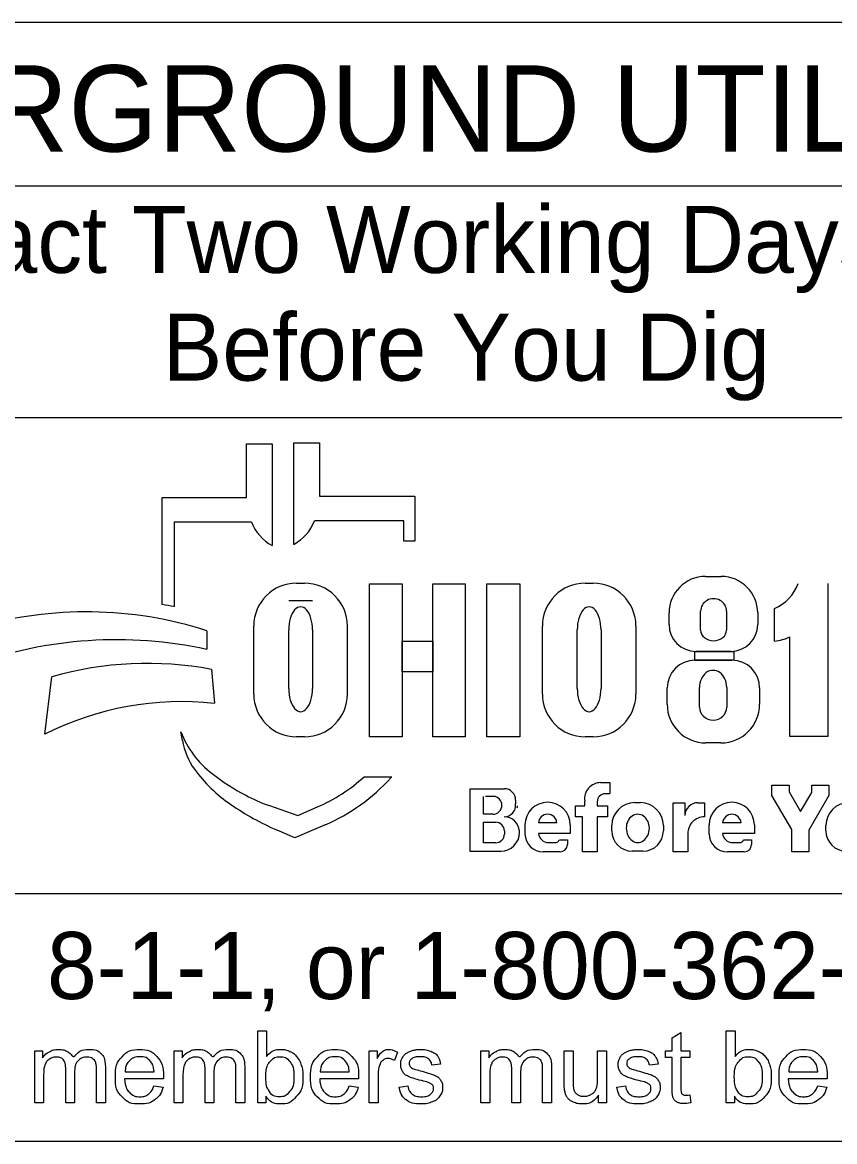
# Model space of a CAD drawing. Extents: x -6.4 to 34, y -1.2 to 22.
# Drawn here: x 3.888 to 5.585, y 3.25 to 5.587 of the extents above; entities that cross this region are included whole.
import ezdxf

# ---------------------------------------------------------------- set-up
doc = ezdxf.new("R2010")
doc.units = 0
doc.layers.add('GM_X_Township', color=7, linetype='Continuous')

msp = doc.modelspace()

# ---------------------------------------------------------------- linework, layer by layer
at = {"layer": 'GM_X_Township'}
for p, q in [((7.25, 5.5875), (3, 5.5875)), ((3, 5.2459), (7.25, 5.2459)), ((3, 4.7625), (7.25, 4.7625)), ((4.356, 4.5955), (4.356, 4.707)), ((4.356, 4.707), (4.4097, 4.707)), ((4.4097, 4.707), (4.4097, 4.4949)), ((4.4553, 4.4972), (4.4553, 4.7093)), ((4.4553, 4.7093), (4.509, 4.7093)), ((4.509, 4.7093), (4.509, 4.5978)), ((4.1801, 4.3716), (4.1801, 4.5955)), ((4.1801, 4.5955), (4.356, 4.5955)), ((4.509, 4.5978), (4.7082, 4.5978)), ((4.7082, 4.5978), (4.7082, 4.504)), ((4.2053, 4.544), (4.2053, 4.3672)), ((4.3664, 4.544), (4.2053, 4.544)), ((4.6849, 4.5464), (4.4986, 4.5464)), ((4.6849, 4.504), (4.6849, 4.5464)), ((4.7082, 4.504), (4.6849, 4.504)), ((5.3156, 4.4303), (5.3483, 4.4303)), ((4.461, 4.4163), (4.4776, 4.4163)), ((5.0641, 4.4163), (5.0806, 4.4163)), ((5.5711, 4.4158), (5.5711, 4.0959)), ((4.4943, 4.3793), (4.4445, 4.3793)), ((5.2393, 4.3297), (5.2393, 4.354)), ((5.3054, 4.3183), (5.3054, 4.3576)), ((5.3596, 4.3576), (5.3596, 4.3183)), ((5.4246, 4.354), (5.4246, 4.3297)), ((5.4595, 4.2951), (5.4595, 4.3633)), ((4.3716, 4.1848), (4.3716, 4.3268)), ((4.567, 4.3268), (4.567, 4.1848)), ((4.9746, 4.1848), (4.9746, 4.3268)), ((5.1701, 4.3268), (5.1701, 4.1848)), ((4.2734, 4.3169), (4.2734, 4.2781)), ((4.4445, 4.1962), (4.4445, 4.3185)), ((4.4943, 4.3185), (4.4943, 4.1962)), ((5.0475, 4.1962), (5.0475, 4.3185)), ((5.0973, 4.3185), (5.0973, 4.1962)), ((5.4919, 4.0959), (5.4919, 4.3045)), ((5.2935, 4.2554), (5.3708, 4.2554)), ((5.3686, 4.2737), (5.2953, 4.2737)), ((4.2833, 4.2363), (4.2896, 4.1654)), ((3.9345, 4.1008), (3.9492, 4.2209)), ((5.2356, 4.1635), (5.2356, 4.1975)), ((5.3031, 4.1575), (5.3031, 4.1984)), ((5.3599, 4.1984), (5.3599, 4.1575)), ((5.4287, 4.1975), (5.4287, 4.1635)), ((4.2222, 4.0879), (4.2192, 4.1058)), ((4.4776, 4.0953), (4.461, 4.0953)), ((5.0806, 4.0953), (5.0641, 4.0953)), ((5.5711, 4.0959), (5.4919, 4.0959)), ((5.3477, 4.0825), (5.3165, 4.0825)), ((4.6025, 4.012), (4.6599, 4.012)), ((5.0964, 3.9997), (5.1158, 3.9997)), ((5.1158, 3.9997), (5.1158, 3.9768)), ((4.8238, 3.8562), (4.8238, 3.987)), ((4.8238, 3.987), (4.895, 3.987)), ((5.1158, 3.9763), (5.1057, 3.9763)), ((5.4544, 3.9942), (5.4902, 3.9942)), ((5.4544, 3.9727), (5.4544, 3.9942)), ((5.4902, 3.9942), (5.4902, 3.9806)), ((5.4902, 3.9806), (5.5143, 3.9392)), ((5.5143, 3.9392), (5.5375, 3.979)), ((5.5375, 3.979), (5.5375, 3.9942)), ((5.5375, 3.9942), (5.5734, 3.9942)), ((5.5734, 3.9942), (5.5734, 3.9727)), ((4.4041, 3.9516), (4.4635, 3.9311)), ((4.8518, 3.9335), (4.8518, 3.9704)), ((4.877, 3.9704), (4.8557, 3.9704)), ((4.9187, 3.9632), (4.9187, 3.9553)), ((5.0438, 3.9284), (5.0438, 3.9514)), ((5.0438, 3.9514), (5.0631, 3.9514)), ((5.0631, 3.9514), (5.0631, 3.9618)), ((5.0892, 3.9598), (5.0892, 3.9514)), ((5.0892, 3.9514), (5.1108, 3.9514)), ((5.1108, 3.9514), (5.1108, 3.9284)), ((5.1676, 3.9579), (5.1797, 3.9579)), ((5.2479, 3.855), (5.2479, 3.9577)), ((5.2479, 3.9577), (5.2724, 3.9577)), ((5.2724, 3.9577), (5.2724, 3.9308)), ((5.2997, 3.9577), (5.3135, 3.9577)), ((5.3135, 3.9577), (5.3135, 3.9281)), ((5.4957, 3.9017), (5.4544, 3.9727)), ((5.5734, 3.9727), (5.5313, 3.9003)), ((4.4635, 3.9311), (4.5045, 3.9489)), ((4.8712, 3.9335), (4.8518, 3.9335)), ((5.0587, 3.9284), (5.0438, 3.9284)), ((5.0587, 3.855), (5.0587, 3.9284)), ((5.1108, 3.9284), (5.0892, 3.9284)), ((5.0892, 3.9284), (5.0892, 3.855)), ((4.5208, 3.9116), (4.4575, 3.8841)), ((4.8518, 3.8741), (4.8518, 3.9169)), ((4.8518, 3.9169), (4.8773, 3.9169)), ((4.9384, 3.893), (4.9384, 3.9114)), ((5.0049, 3.9154), (4.9664, 3.9154)), ((5.0329, 3.9114), (5.0329, 3.8937)), ((5.1198, 3.8993), (5.1198, 3.9101)), ((5.2276, 3.9101), (5.2276, 3.8993)), ((5.3233, 3.893), (5.3233, 3.9114)), ((5.3899, 3.9154), (5.3513, 3.9154)), ((5.4178, 3.9114), (5.4178, 3.8937)), ((5.5672, 3.8993), (5.5672, 3.9101)), ((4.4575, 3.8841), (4.4201, 3.9005)), ((4.8954, 3.8988), (4.8954, 3.8924)), ((4.9268, 3.8959), (4.9268, 3.8956)), ((5.0329, 3.8937), (4.9665, 3.8937)), ((5.2784, 3.8932), (5.2784, 3.855)), ((5.4178, 3.8937), (5.3514, 3.8937)), ((5.4957, 3.855), (5.4957, 3.9017)), ((5.5313, 3.9003), (5.5313, 3.855)), ((4.8771, 3.8741), (4.8518, 3.8741)), ((4.9874, 3.8745), (5.0015, 3.8745)), ((5.0101, 3.8801), (5.0269, 3.8801)), ((5.0269, 3.8801), (5.0269, 3.8703)), ((5.3723, 3.8745), (5.3864, 3.8745)), ((5.395, 3.8801), (5.4119, 3.8801)), ((5.4119, 3.8801), (5.4119, 3.8703)), ((4.8875, 3.8562), (4.8238, 3.8562)), ((5.0117, 3.855), (4.9763, 3.855)), ((5.0892, 3.855), (5.0587, 3.855)), ((5.1848, 3.8566), (5.1626, 3.8566)), ((5.2784, 3.855), (5.2479, 3.855)), ((5.3966, 3.855), (5.3612, 3.855)), ((5.5313, 3.855), (5.4957, 3.855)), ((7.25, 3.7678), (3, 3.7678)), ((7.25, 3.25), (3, 3.25))]:
    msp.add_line(p, q, dxfattribs=at)
for points in [[(4.6135, 4.4152), (4.6814, 4.4152), (4.6814, 4.0953), (4.6135, 4.0953)], [(4.7456, 4.4152), (4.8136, 4.4152), (4.8136, 4.0953), (4.7456, 4.0953)], [(4.8589, 4.4152), (4.9277, 4.4152), (4.9277, 4.0953), (4.8589, 4.0953)], [(4.6814, 4.2954), (4.7456, 4.2954), (4.7456, 4.2314), (4.6814, 4.2314)], [(5.2931, 4.2737), (5.3748, 4.2737), (5.3748, 4.2552), (5.2931, 4.2552)]]:
    msp.add_lwpolyline(points, close=True, dxfattribs=at)
for points in [[(4.3968, 3.3311), (4.3798, 3.3311), (4.3798, 3.4813), (4.3982, 3.4813), (4.3982, 3.4277)], [(5.2458, 3.363), (5.2458, 3.4256), (5.2321, 3.4256), (5.2321, 3.4399), (5.2458, 3.4399), (5.2458, 3.4669), (5.2642, 3.4779), (5.2642, 3.4399), (5.2826, 3.4399), (5.2826, 3.4256), (5.2642, 3.4256), (5.2642, 3.3619)], [(5.3759, 3.3311), (5.3588, 3.3311), (5.3588, 3.4813), (5.3773, 3.4813), (5.3773, 3.4277)], [(3.9137, 3.3311), (3.9137, 3.4399), (3.9302, 3.4399), (3.9302, 3.4246)], [(4.2051, 3.3311), (4.2051, 3.4399), (4.2216, 3.4399), (4.2216, 3.4246)], [(4.6129, 3.3311), (4.6129, 3.4399), (4.6295, 3.4399), (4.6295, 3.4234)], [(4.6719, 3.4365), (4.6655, 3.4194)], [(4.8461, 3.3311), (4.8461, 3.4399), (4.8626, 3.4399), (4.8626, 3.4246)], [(5.0204, 3.3725), (5.0204, 3.4399), (5.0388, 3.4399), (5.0388, 3.3796)], [(5.0901, 3.3817), (5.0901, 3.4399), (5.1085, 3.4399), (5.1085, 3.3311), (5.0921, 3.3311)], [(3.9968, 3.3943), (3.9968, 3.3311), (3.9784, 3.3311), (3.9784, 3.4017)], [(4.0613, 3.4058), (4.0613, 3.3311), (4.0428, 3.3311), (4.0428, 3.3996)], [(4.1024, 3.3959), (4.1631, 3.3959)], [(4.2882, 3.3943), (4.2882, 3.3311), (4.2698, 3.3311), (4.2698, 3.4017)], [(4.3526, 3.4058), (4.3526, 3.3311), (4.3342, 3.3311), (4.3342, 3.3996)], [(4.5103, 3.3959), (4.5711, 3.3959)], [(4.7619, 3.4118), (4.7438, 3.4094)], [(4.9292, 3.3943), (4.9292, 3.3311), (4.9108, 3.3311), (4.9108, 3.4017)], [(4.9936, 3.4058), (4.9936, 3.3311), (4.9752, 3.3311), (4.9752, 3.3996)], [(5.2165, 3.4118), (5.1984, 3.4094)], [(5.4894, 3.3959), (5.5502, 3.3959)], [(3.9322, 3.3875), (3.9322, 3.3311), (3.9137, 3.3311)], [(4.1825, 3.3808), (4.1013, 3.3808)], [(4.1629, 3.3662), (4.182, 3.3638)], [(4.2235, 3.3875), (4.2235, 3.3311), (4.2051, 3.3311)], [(4.5905, 3.3808), (4.5093, 3.3808)], [(4.5709, 3.3662), (4.59, 3.3638)], [(4.6313, 3.3881), (4.6313, 3.3311), (4.6129, 3.3311)], [(4.6755, 3.3636), (4.6937, 3.3665)], [(4.8645, 3.3875), (4.8645, 3.3311), (4.8461, 3.3311)], [(5.1301, 3.3636), (5.1483, 3.3665)], [(5.5695, 3.3808), (5.4884, 3.3808)], [(5.55, 3.3662), (5.569, 3.3638)], [(4.3968, 3.3447), (4.3968, 3.3311)], [(5.0921, 3.3311), (5.0921, 3.3472)], [(5.2826, 3.3475), (5.2852, 3.3312)], [(5.3759, 3.3447), (5.3759, 3.3311)]]:
    msp.add_lwpolyline(points, dxfattribs=at)
for centre, radius, start, end in [((4.4578, 4.5808), 0.0985, 201.9296, 240.7469), ((4.4072, 4.5831), 0.0985, 299.2531, 338.0704), ((5.3156, 4.354), 0.0763, 90, 180), ((5.3483, 4.354), 0.0763, 0, 90), ((4.461, 4.3268), 0.0895, 90, 180), ((4.4776, 4.3268), 0.0895, 0, 90), ((5.0641, 4.3268), 0.0895, 90, 180), ((5.0806, 4.3268), 0.0895, 0, 90), ((5.4256, 4.445), 0.0885, 292.5572, 340.7355), ((4.0519, 3.5626), 0.8191, 79.2074, 81.0007), ((4.0222, 3.5373), 0.8191, 72.1402, 106.3144), ((5.2953, 4.3297), 0.056, 180, 270), ((5.3686, 4.3297), 0.056, 270, 0), ((5.4516, 4.3833), 0.0885, 275.1733, 297.0931), ((4.0852, 3.4062), 0.8919, 77.8238, 109.8274), ((5.2935, 4.1975), 0.0579, 90, 180), ((5.3708, 4.1975), 0.0579, 0, 90), ((4.1492, 3.5165), 0.7322, 79.44, 105.8467), ((4.461, 4.1848), 0.0895, 180, 270), ((4.4776, 4.1848), 0.0895, 270, 0), ((5.0641, 4.1848), 0.0895, 180, 270), ((5.0806, 4.1848), 0.0895, 270, 0), ((4.2212, 3.5333), 0.6357, 83.8248, 116.8021), ((5.3165, 4.1635), 0.081, 180, 270), ((5.3477, 4.1635), 0.081, 270, 0), ((4.4066, 4.1779), 0.2008, 201.0457, 232.5314), ((4.3635, 4.112), 0.1433, 189.6817, 216.0884), ((4.4972, 4.2094), 0.3088, 216.0884, 235.7167), ((4.5991, 4.4291), 0.5173, 232.5314, 241.794), ((4.3611, 4.2794), 0.3602, 293.4582, 312.0712), ((4.3611, 4.2794), 0.401, 293.4582, 317.8286), ((5.0964, 3.9662), 0.0335, 90, 187.5187), ((4.895, 3.9632), 0.0238, 0, 90), ((5.1057, 3.9598), 0.0165, 90, 180), ((4.6637, 4.4536), 0.6044, 235.7167, 246.2325), ((4.5139, 4.2703), 0.3371, 241.794, 250.9821), ((4.8712, 3.9522), 0.0187, 270, 2.0582), ((4.873, 3.9535), 0.0169, 357.8325, 90), ((4.8946, 3.9525), 0.0243, 270, 6.6529), ((4.9052, 3.951), 0.0175, 347.4023, 0), ((4.9856, 3.9114), 0.0473, 0, 180), ((5.1676, 3.9101), 0.0478, 90, 180), ((5.1797, 3.9101), 0.0478, 0, 90), ((5.2993, 3.9308), 0.0269, 89.2449, 180), ((5.3705, 3.9114), 0.0473, 0, 180), ((5.615, 3.9101), 0.0478, 90, 180), ((4.8947, 3.8961), 0.0321, 4.0748, 90), ((4.9857, 3.9144), 0.0193, 2.9632, 177.0368), ((5.3133, 3.8932), 0.0349, 89.6033, 180), ((5.3706, 3.9144), 0.0193, 2.9632, 177.0368), ((4.8773, 3.8988), 0.0181, 0, 90), ((4.8771, 3.8924), 0.0184, 270, 0), ((4.8875, 3.8956), 0.0393, 270, 0), ((4.8938, 3.8959), 0.033, 0, 11.7502), ((4.9763, 3.893), 0.038, 180, 270), ((4.9874, 3.8955), 0.021, 184.827, 270), ((5.1626, 3.8993), 0.0428, 180, 270), ((5.1848, 3.8993), 0.0428, 270, 0), ((5.3612, 3.893), 0.038, 180, 270), ((5.3723, 3.8955), 0.021, 184.827, 270), ((5.61, 3.8993), 0.0428, 180, 270), ((5.0015, 3.8839), 0.00938, 270, 335.9979), ((5.0117, 3.8703), 0.0152, 270, 0), ((5.3864, 3.8839), 0.00938, 270, 335.9979), ((5.3966, 3.8703), 0.0152, 270, 0)]:
    msp.add_arc(centre, radius, start, end, dxfattribs=at)
for centre, major_axis, ratio, start_param, end_param in [((5.3325, 4.3576), (0.0271, 0), 0.969373, 0, 3.141593), ((4.4694, 4.3185), (0, 0.0484), 0.514403, 4.712389, 7.853982), ((5.0724, 4.3185), (0, 0.0484), 0.514403, 4.712389, 7.853982), ((5.3325, 4.3183), (0.0271, 0), 0.818453, 3.141593, 6.283185), ((5.3315, 4.1984), (0, 0.0358), 0.794529, 4.712389, 7.853982), ((4.4694, 4.1962), (0, 0.0484), 0.514403, 1.570796, 4.712389), ((5.0724, 4.1962), (0, 0.0484), 0.514403, 1.570796, 4.712389), ((5.3315, 4.1575), (0.0284, 0), 0.959837, 3.141593, 6.283185), ((5.1741, 3.9047), (0, 0.029), 0.832186, 4.712389, 7.853982), ((5.1741, 3.9047), (0, 0.0302), 0.797287, 1.570796, 4.712389)]:
    msp.add_ellipse(centre, major_axis=major_axis, ratio=ratio, start_param=start_param, end_param=end_param, dxfattribs=at)
for points in [[(3.9302, 3.4246), (3.9353, 3.4326), (3.9438, 3.4375), (3.9523, 3.4423), (3.9632, 3.4423), (3.9753, 3.4423), (3.983, 3.4373), (3.9908, 3.4323), (3.994, 3.4232), (4.0069, 3.4423), (4.0276, 3.4423), (4.0438, 3.4423), (4.0525, 3.4334), (4.0613, 3.4244), (4.0613, 3.4058)], [(4.182, 3.3638), (4.1775, 3.3471), (4.1653, 3.3379), (4.1531, 3.3287), (4.1341, 3.3287), (4.1103, 3.3287), (4.0963, 3.3434), (4.0823, 3.3581), (4.0823, 3.3846), (4.0823, 3.412), (4.0965, 3.4272), (4.1106, 3.4423), (4.1331, 3.4423), (4.1549, 3.4423), (4.1688, 3.4275), (4.1826, 3.4126), (4.1826, 3.3857), (4.1826, 3.384), (4.1825, 3.3808)], [(4.2216, 3.4246), (4.2267, 3.4326), (4.2352, 3.4375), (4.2437, 3.4423), (4.2546, 3.4423), (4.2667, 3.4423), (4.2744, 3.4373), (4.2821, 3.4323), (4.2853, 3.4232), (4.2983, 3.4423), (4.319, 3.4423), (4.3352, 3.4423), (4.3439, 3.4334), (4.3526, 3.4244), (4.3526, 3.4058)], [(4.3982, 3.4277), (4.4099, 3.4423), (4.428, 3.4423), (4.438, 3.4423), (4.447, 3.4383), (4.4559, 3.4343), (4.4617, 3.4269), (4.4675, 3.4196), (4.4708, 3.4093), (4.4741, 3.3989), (4.4741, 3.3872), (4.4741, 3.3592), (4.4602, 3.344), (4.4464, 3.3287), (4.427, 3.3287), (4.4078, 3.3287), (4.3968, 3.3447)], [(4.59, 3.3638), (4.5855, 3.3471), (4.5733, 3.3379), (4.5611, 3.3287), (4.5421, 3.3287), (4.5183, 3.3287), (4.5043, 3.3434), (4.4903, 3.3581), (4.4903, 3.3846), (4.4903, 3.412), (4.5045, 3.4272), (4.5186, 3.4423), (4.5411, 3.4423), (4.5629, 3.4423), (4.5767, 3.4275), (4.5906, 3.4126), (4.5906, 3.3857), (4.5906, 3.384), (4.5905, 3.3808)], [(4.6295, 3.4234), (4.6358, 3.435), (4.6412, 3.4387), (4.6466, 3.4423), (4.653, 3.4423), (4.6623, 3.4423), (4.6719, 3.4365)], [(4.6937, 3.3665), (4.6952, 3.3555), (4.7023, 3.3496), (4.7093, 3.3438), (4.7219, 3.3438), (4.7347, 3.3438), (4.7409, 3.349), (4.747, 3.3542), (4.747, 3.3611), (4.747, 3.3674), (4.7416, 3.371), (4.7378, 3.3735), (4.7227, 3.3772), (4.7024, 3.3824), (4.6945, 3.3861), (4.6867, 3.3898), (4.6826, 3.3964), (4.6786, 3.403), (4.6786, 3.411), (4.6786, 3.4183), (4.6819, 3.4245), (4.6853, 3.4307), (4.691, 3.4348), (4.6953, 3.4379), (4.7027, 3.4401), (4.7102, 3.4423), (4.7187, 3.4423), (4.7315, 3.4423), (4.7412, 3.4386), (4.7509, 3.435), (4.7555, 3.4287), (4.7602, 3.4223), (4.7619, 3.4118)], [(4.8626, 3.4246), (4.8677, 3.4326), (4.8762, 3.4375), (4.8847, 3.4423), (4.8956, 3.4423), (4.9077, 3.4423), (4.9154, 3.4373), (4.9231, 3.4323), (4.9263, 3.4232), (4.9393, 3.4423), (4.96, 3.4423), (4.9762, 3.4423), (4.9849, 3.4334), (4.9936, 3.4244), (4.9936, 3.4058)], [(5.1483, 3.3665), (5.1498, 3.3555), (5.1568, 3.3496), (5.1639, 3.3438), (5.1765, 3.3438), (5.1893, 3.3438), (5.1954, 3.349), (5.2016, 3.3542), (5.2016, 3.3611), (5.2016, 3.3674), (5.1961, 3.371), (5.1923, 3.3735), (5.1773, 3.3772), (5.157, 3.3824), (5.1491, 3.3861), (5.1413, 3.3898), (5.1372, 3.3964), (5.1332, 3.403), (5.1332, 3.411), (5.1332, 3.4183), (5.1365, 3.4245), (5.1398, 3.4307), (5.1456, 3.4348), (5.1499, 3.4379), (5.1573, 3.4401), (5.1648, 3.4423), (5.1733, 3.4423), (5.1861, 3.4423), (5.1958, 3.4386), (5.2055, 3.435), (5.2101, 3.4287), (5.2147, 3.4223), (5.2165, 3.4118)], [(5.3773, 3.4277), (5.3889, 3.4423), (5.4071, 3.4423), (5.4171, 3.4423), (5.426, 3.4383), (5.435, 3.4343), (5.4408, 3.4269), (5.4466, 3.4196), (5.4499, 3.4093), (5.4531, 3.3989), (5.4531, 3.3872), (5.4531, 3.3592), (5.4393, 3.344), (5.4255, 3.3287), (5.4061, 3.3287), (5.3868, 3.3287), (5.3759, 3.3447)], [(5.569, 3.3638), (5.5645, 3.3471), (5.5523, 3.3379), (5.5401, 3.3287), (5.5212, 3.3287), (5.4973, 3.3287), (5.4834, 3.3434), (5.4694, 3.3581), (5.4694, 3.3846), (5.4694, 3.412), (5.4835, 3.4272), (5.4976, 3.4423), (5.5202, 3.4423), (5.542, 3.4423), (5.5558, 3.4275), (5.5696, 3.4126), (5.5696, 3.3857), (5.5696, 3.384), (5.5695, 3.3808)], [(3.9784, 3.4017), (3.9784, 3.414), (3.9739, 3.4202), (3.9694, 3.4263), (3.9591, 3.4263), (3.9513, 3.4263), (3.9447, 3.4222), (3.9381, 3.4181), (3.9351, 3.4102), (3.9322, 3.4024), (3.9322, 3.3875)], [(4.0428, 3.3996), (4.0428, 3.4107), (4.041, 3.4155), (4.0392, 3.4204), (4.0345, 3.4233), (4.0298, 3.4263), (4.0235, 3.4263), (4.012, 3.4263), (4.0044, 3.4187), (3.9968, 3.4111), (3.9968, 3.3943)], [(4.1631, 3.3959), (4.1619, 3.4097), (4.1562, 3.4165), (4.1473, 3.4272), (4.1333, 3.4272), (4.1206, 3.4272), (4.1119, 3.4187), (4.1033, 3.4102), (4.1024, 3.3959)], [(4.2698, 3.4017), (4.2698, 3.414), (4.2653, 3.4202), (4.2607, 3.4263), (4.2505, 3.4263), (4.2427, 3.4263), (4.2361, 3.4222), (4.2295, 3.4181), (4.2265, 3.4102), (4.2235, 3.4024), (4.2235, 3.3875)], [(4.3342, 3.3996), (4.3342, 3.4107), (4.3324, 3.4155), (4.3306, 3.4204), (4.3259, 3.4233), (4.3212, 3.4263), (4.3148, 3.4263), (4.3034, 3.4263), (4.2958, 3.4187), (4.2882, 3.4111), (4.2882, 3.3943)], [(4.3966, 3.3863), (4.3966, 3.3668), (4.4019, 3.3581), (4.4106, 3.3438), (4.4254, 3.3438), (4.4375, 3.3438), (4.4463, 3.3543), (4.4551, 3.3648), (4.4551, 3.3856), (4.4551, 3.4069), (4.4466, 3.4171), (4.4382, 3.4272), (4.4262, 3.4272), (4.4142, 3.4272), (4.4054, 3.4167), (4.3966, 3.4062), (4.3966, 3.3863)], [(4.5711, 3.3959), (4.5699, 3.4097), (4.5641, 3.4165), (4.5553, 3.4272), (4.5413, 3.4272), (4.5286, 3.4272), (4.5199, 3.4187), (4.5113, 3.4102), (4.5103, 3.3959)], [(4.6655, 3.4194), (4.6588, 3.4233), (4.652, 3.4233), (4.646, 3.4233), (4.6412, 3.4197), (4.6364, 3.4161), (4.6344, 3.4096), (4.6313, 3.3998), (4.6313, 3.3881)], [(4.7438, 3.4094), (4.7426, 3.4178), (4.7367, 3.4225), (4.7308, 3.4272), (4.72, 3.4272), (4.7073, 3.4272), (4.7019, 3.423), (4.6964, 3.4188), (4.6964, 3.4132), (4.6964, 3.4096), (4.6987, 3.4067), (4.7009, 3.4037), (4.7058, 3.4018), (4.7085, 3.4008), (4.7221, 3.3971), (4.7417, 3.3918), (4.7494, 3.3885), (4.7572, 3.3852), (4.7616, 3.3788), (4.766, 3.3725), (4.766, 3.3631), (4.766, 3.3539), (4.7606, 3.3457), (4.7552, 3.3376), (4.7451, 3.3332), (4.7349, 3.3287), (4.7221, 3.3287), (4.7008, 3.3287), (4.6897, 3.3375), (4.6786, 3.3463), (4.6755, 3.3636)], [(4.9108, 3.4017), (4.9108, 3.414), (4.9063, 3.4202), (4.9017, 3.4263), (4.8915, 3.4263), (4.8837, 3.4263), (4.8771, 3.4222), (4.8705, 3.4181), (4.8675, 3.4102), (4.8645, 3.4024), (4.8645, 3.3875)], [(4.9752, 3.3996), (4.9752, 3.4107), (4.9734, 3.4155), (4.9716, 3.4204), (4.9669, 3.4233), (4.9622, 3.4263), (4.9558, 3.4263), (4.9444, 3.4263), (4.9368, 3.4187), (4.9292, 3.4111), (4.9292, 3.3943)], [(5.1984, 3.4094), (5.1972, 3.4178), (5.1913, 3.4225), (5.1854, 3.4272), (5.1746, 3.4272), (5.1619, 3.4272), (5.1564, 3.423), (5.151, 3.4188), (5.151, 3.4132), (5.151, 3.4096), (5.1533, 3.4067), (5.1555, 3.4037), (5.1603, 3.4018), (5.1631, 3.4008), (5.1766, 3.3971), (5.1962, 3.3918), (5.204, 3.3885), (5.2117, 3.3852), (5.2162, 3.3788), (5.2206, 3.3725), (5.2206, 3.3631), (5.2206, 3.3539), (5.2152, 3.3457), (5.2098, 3.3376), (5.1996, 3.3332), (5.1895, 3.3287), (5.1767, 3.3287), (5.1554, 3.3287), (5.1443, 3.3375), (5.1331, 3.3463), (5.1301, 3.3636)], [(5.3757, 3.3863), (5.3757, 3.3668), (5.381, 3.3581), (5.3897, 3.3438), (5.4045, 3.3438), (5.4166, 3.3438), (5.4253, 3.3543), (5.4341, 3.3648), (5.4341, 3.3856), (5.4341, 3.4069), (5.4257, 3.4171), (5.4173, 3.4272), (5.4053, 3.4272), (5.3932, 3.4272), (5.3844, 3.4167), (5.3757, 3.4062), (5.3757, 3.3863)], [(5.5502, 3.3959), (5.549, 3.4097), (5.5432, 3.4165), (5.5344, 3.4272), (5.5204, 3.4272), (5.5077, 3.4272), (5.499, 3.4187), (5.4903, 3.4102), (5.4894, 3.3959)], [(4.1013, 3.3808), (4.1024, 3.3629), (4.1115, 3.3533), (4.1206, 3.3438), (4.1342, 3.3438), (4.1444, 3.3438), (4.1515, 3.3492), (4.1587, 3.3545), (4.1629, 3.3662)], [(4.5093, 3.3808), (4.5103, 3.3629), (4.5195, 3.3533), (4.5286, 3.3438), (4.5422, 3.3438), (4.5524, 3.3438), (4.5595, 3.3492), (4.5667, 3.3545), (4.5709, 3.3662)], [(5.0921, 3.3472), (5.0794, 3.3287), (5.0576, 3.3287), (5.048, 3.3287), (5.0396, 3.3324), (5.0313, 3.3361), (5.0272, 3.3417), (5.0232, 3.3472), (5.0215, 3.3553), (5.0204, 3.3608), (5.0204, 3.3725)], [(5.0388, 3.3796), (5.0388, 3.3652), (5.04, 3.3602), (5.0417, 3.3529), (5.0473, 3.3488), (5.053, 3.3446), (5.0613, 3.3446), (5.0695, 3.3446), (5.0768, 3.3489), (5.0841, 3.3531), (5.0871, 3.3604), (5.0901, 3.3677), (5.0901, 3.3817)], [(5.4884, 3.3808), (5.4894, 3.3629), (5.4985, 3.3533), (5.5077, 3.3438), (5.5213, 3.3438), (5.5314, 3.3438), (5.5386, 3.3492), (5.5458, 3.3545), (5.55, 3.3662)], [(5.2852, 3.3312), (5.2775, 3.3296), (5.2713, 3.3296), (5.2613, 3.3296), (5.2558, 3.3328), (5.2503, 3.336), (5.248, 3.3412), (5.2458, 3.3463), (5.2458, 3.363)], [(5.2642, 3.3619), (5.2642, 3.354), (5.2652, 3.3517), (5.2661, 3.3494), (5.2683, 3.3481), (5.2705, 3.3468), (5.2746, 3.3468), (5.2776, 3.3468), (5.2826, 3.3475)]]:
    msp.add_open_spline(points, degree=3, dxfattribs=at)

# ---------------------------------------------------------------- texts
for s, height, p in [('UNDERGROUND UTILITIES', 0.18, (3.1282, 5.3178)), ('Contact Two Working Days', 0.14, (3.4196, 5.0643)), ('Before You Dig', 0.14, (4.1808, 4.8393)), ('OHIO811, 8-1-1, or 1-800-362-2764', 0.14, (3.0445, 3.5478))]:
    msp.add_text(s, height=height, dxfattribs=at).set_placement(p)

doc.saveas('drawing.dxf')
